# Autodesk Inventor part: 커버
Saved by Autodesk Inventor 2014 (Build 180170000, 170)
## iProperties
Created: 2026-04
Part Number: 커버
Material: 일반
Document SubType Name: Modeling
Designer: dg
Density: 1 g/cm^3
Appearance: 기본값
Author: dg
Author: jhkim
Creation Date: 2026-03-27
Sending System: Autodesk Inventor 2026
Preprocessor: ST-DEVELOPER v20.1
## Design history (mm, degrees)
node "커버1"
node "솔리드1"
node "기준1"
